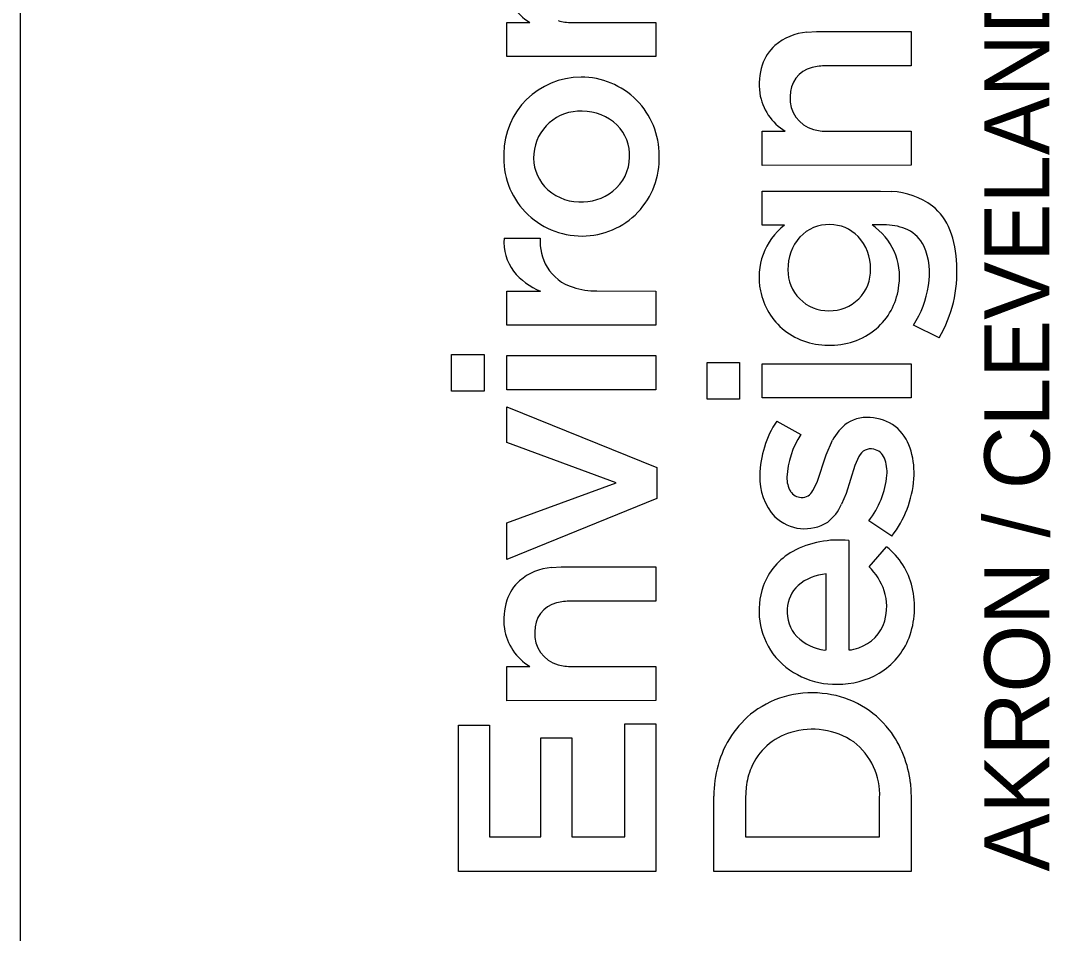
# Model space of a CAD drawing. Extents: x 0 to 34, y 0 to 22.
# Drawn here: x 32 to 32.901, y 2.584 to 3.382 of the extents above; entities that cross this region are included whole.
import ezdxf

# ---------------------------------------------------------------- set-up
doc = ezdxf.new("R2010")
doc.units = 0
doc.layers.add('SH_Border', color=7, linetype='Continuous')
doc.layers.add('SH_Data', color=7, linetype='Continuous')

msp = doc.modelspace()

# ---------------------------------------------------------------- linework, layer by layer
at = {"layer": 'SH_Border'}
msp.add_line((32, 0.5), (32, 21.5), dxfattribs=at)
at = {"layer": 'SH_Data'}
for p, q in [((32.42542, 3.38066), (32.44552, 3.38071)), ((32.42542, 3.35086), (32.42542, 3.38066)), ((32.48222, 3.38071), (32.55569, 3.38071)), ((32.55569, 3.38071), (32.55571, 3.35096)), ((32.68784, 3.3722), (32.69634, 3.37266)), ((32.69634, 3.37266), (32.77916, 3.37266)), ((32.77916, 3.37266), (32.77917, 3.34287)), ((32.55571, 3.35096), (32.42542, 3.35086)), ((32.77917, 3.34287), (32.70485, 3.3428)), ((32.64888, 3.2855), (32.66897, 3.28555)), ((32.64888, 3.25569), (32.64888, 3.2855)), ((32.70568, 3.28555), (32.77915, 3.28555)), ((32.77915, 3.28555), (32.77917, 3.25579)), ((32.77917, 3.25579), (32.64888, 3.25569)), ((32.6489, 3.20336), (32.64889, 3.23322)), ((32.64889, 3.23322), (32.75236, 3.23322)), ((32.75236, 3.23322), (32.76191, 3.23285)), ((32.66836, 3.20336), (32.6489, 3.20336)), ((32.75763, 3.20356), (32.74487, 3.20361)), ((32.42299, 3.19193), (32.45454, 3.19193)), ((32.42542, 3.14577), (32.45473, 3.14579)), ((32.42542, 3.11593), (32.42542, 3.14577)), ((32.50413, 3.14581), (32.55571, 3.14573)), ((32.55571, 3.14573), (32.55565, 3.11593)), ((32.55565, 3.11593), (32.42542, 3.11593)), ((32.8036, 3.10491), (32.7812, 3.11598)), ((32.37705, 3.05818), (32.37705, 3.09026)), ((32.37705, 3.09026), (32.40543, 3.09026)), ((32.40543, 3.09026), (32.40543, 3.05818)), ((32.42542, 3.05942), (32.42542, 3.08928)), ((32.42542, 3.08928), (32.55571, 3.08928)), ((32.55571, 3.08928), (32.55571, 3.05942)), ((32.60051, 3.05111), (32.60051, 3.08319)), ((32.60051, 3.08319), (32.62889, 3.08319)), ((32.62889, 3.08319), (32.62889, 3.05111)), ((32.64888, 3.05234), (32.64888, 3.0822)), ((32.64888, 3.0822), (32.77917, 3.0822)), ((32.77917, 3.0822), (32.77917, 3.05234)), ((32.40543, 3.05818), (32.37705, 3.05818)), ((32.55571, 3.05942), (32.42542, 3.05942)), ((32.62889, 3.05111), (32.60051, 3.05111)), ((32.77917, 3.05234), (32.64888, 3.05234)), ((32.42542, 3.01327), (32.42542, 3.0446)), ((32.42542, 3.0446), (32.5567, 2.9913)), ((32.66151, 3.03207), (32.68268, 3.02025)), ((32.52117, 2.97798), (32.42542, 3.01327)), ((32.70483, 3.00258), (32.71036, 3.01526)), ((32.69675, 2.97868), (32.70483, 3.00258)), ((32.73342, 3.00101), (32.72985, 2.9933)), ((32.5567, 2.9913), (32.5567, 2.96441)), ((32.72985, 2.9933), (32.72213, 2.96882)), ((32.42542, 2.94294), (32.52117, 2.97798)), ((32.69299, 2.97117), (32.69675, 2.97868)), ((32.5567, 2.96441), (32.42542, 2.91086)), ((32.72213, 2.96882), (32.71822, 2.95921)), ((32.42542, 2.91086), (32.42542, 2.94294)), ((32.76214, 2.93141), (32.74198, 2.94469)), ((32.72453, 2.92747), (32.72463, 2.83195)), ((32.74228, 2.90465), (32.75768, 2.922)), ((32.46439, 2.90397), (32.47289, 2.90443)), ((32.47289, 2.90443), (32.55571, 2.90443)), ((32.55571, 2.90443), (32.55571, 2.87465)), ((32.70489, 2.83182), (32.70489, 2.89834)), ((32.55571, 2.87465), (32.4814, 2.87457)), ((32.70361, 2.83165), (32.70489, 2.83182)), ((32.42542, 2.81728), (32.44552, 2.81733)), ((32.42542, 2.78747), (32.42542, 2.81728)), ((32.48222, 2.81733), (32.55569, 2.81733)), ((32.55569, 2.81733), (32.55571, 2.78756)), ((32.55571, 2.78756), (32.42542, 2.78747)), ((32.38298, 2.63791), (32.38298, 2.76598)), ((32.38298, 2.76598), (32.41012, 2.76598)), ((32.41012, 2.76598), (32.41012, 2.66827)), ((32.52857, 2.66827), (32.52857, 2.76722)), ((32.52857, 2.76722), (32.55571, 2.76722)), ((32.55571, 2.76722), (32.55571, 2.63791)), ((32.45503, 2.66827), (32.45503, 2.75488)), ((32.45503, 2.75488), (32.48218, 2.75488)), ((32.48218, 2.75488), (32.48218, 2.66827)), ((32.77847, 2.71497), (32.77917, 2.7021)), ((32.60643, 2.63799), (32.60644, 2.704)), ((32.63465, 2.71178), (32.63407, 2.7023)), ((32.63407, 2.7023), (32.63407, 2.66838)), ((32.75149, 2.66834), (32.75153, 2.70239)), ((32.77917, 2.7021), (32.77917, 2.638)), ((32.41012, 2.66827), (32.45503, 2.66827)), ((32.48218, 2.66827), (32.52857, 2.66827)), ((32.63407, 2.66838), (32.75149, 2.66834)), ((32.55571, 2.63791), (32.38298, 2.63791)), ((32.77917, 2.638), (32.60643, 2.63799))]:
    msp.add_line(p, q, dxfattribs=at)
for points in [[(32.42542, 3.35086), (32.42542, 3.38066), (32.44552, 3.38071)], [(32.48222, 3.38071), (32.55569, 3.38071), (32.55571, 3.35096), (32.42542, 3.35086)], [(32.68784, 3.3722), (32.69634, 3.37266), (32.77916, 3.37266), (32.77917, 3.34287), (32.70485, 3.3428)], [(32.64888, 3.25569), (32.64888, 3.2855), (32.66897, 3.28555)], [(32.70568, 3.28555), (32.77915, 3.28555), (32.77917, 3.25579), (32.64888, 3.25569)], [(32.66836, 3.20336), (32.6489, 3.20336), (32.64889, 3.23322), (32.75236, 3.23322), (32.76191, 3.23285)], [(32.75763, 3.20356), (32.74487, 3.20361)], [(32.42299, 3.19193), (32.45454, 3.19193)], [(32.50413, 3.14581), (32.55571, 3.14573), (32.55565, 3.11593), (32.42542, 3.11593)], [(32.42542, 3.11593), (32.42542, 3.14577), (32.45473, 3.14579)], [(32.8036, 3.10491), (32.7812, 3.11598)], [(32.66151, 3.03207), (32.68268, 3.02025)], [(32.69299, 2.97117), (32.69675, 2.97868), (32.70483, 3.00258), (32.71036, 3.01526)], [(32.73342, 3.00101), (32.72985, 2.9933), (32.72213, 2.96882), (32.71822, 2.95921)], [(32.76214, 2.93141), (32.74198, 2.94469)], [(32.72453, 2.92747), (32.72463, 2.83195)], [(32.74228, 2.90465), (32.75768, 2.922)], [(32.46439, 2.90397), (32.47289, 2.90443), (32.55571, 2.90443), (32.55571, 2.87465), (32.4814, 2.87457)], [(32.70361, 2.83165), (32.70489, 2.83182), (32.70489, 2.89834)], [(32.42542, 2.78747), (32.42542, 2.81728), (32.44552, 2.81733)], [(32.48222, 2.81733), (32.55569, 2.81733), (32.55571, 2.78756), (32.42542, 2.78747)], [(32.77847, 2.71497), (32.77917, 2.7021), (32.77917, 2.638), (32.60643, 2.63799)], [(32.60643, 2.63799), (32.60644, 2.704)], [(32.63465, 2.71178), (32.63407, 2.7023), (32.63407, 2.66838), (32.75149, 2.66834), (32.75153, 2.70239)]]:
    msp.add_lwpolyline(points, dxfattribs=at)
for points in [[(32.37705, 3.05818), (32.37705, 3.09026), (32.40543, 3.09026), (32.40543, 3.05818)], [(32.42542, 3.05942), (32.42542, 3.08928), (32.55571, 3.08928), (32.55571, 3.05942)], [(32.60051, 3.05111), (32.60051, 3.08319), (32.62889, 3.08319), (32.62889, 3.05111)], [(32.64888, 3.05234), (32.64888, 3.0822), (32.77917, 3.0822), (32.77917, 3.05234)], [(32.42542, 2.91086), (32.42542, 2.94294), (32.52117, 2.97798), (32.42542, 3.01327), (32.42542, 3.0446), (32.5567, 2.9913), (32.5567, 2.96441)], [(32.38298, 2.63791), (32.38298, 2.76598), (32.41012, 2.76598), (32.41012, 2.66827), (32.45503, 2.66827), (32.45503, 2.75488), (32.48218, 2.75488), (32.48218, 2.66827), (32.52857, 2.66827), (32.52857, 2.76722), (32.55571, 2.76722), (32.55571, 2.63791)]]:
    msp.add_lwpolyline(points, close=True, dxfattribs=at)
for centre, radius, start, end in [((32.47027, 3.42141), 0.04763, 188.96462, 238.69865), ((32.47027, 3.42141), 0.04763, 188.96462, 238.69865), ((32.48183, 3.42286), 0.04215, 254.08913, 270.52838), ((32.48183, 3.42286), 0.04215, 254.08913, 270.52838), ((32.69216, 3.32251), 0.04988, 94.97056, 130.22484), ((32.69216, 3.32251), 0.04988, 94.97056, 130.22484), ((32.68694, 3.33085), 0.04016, 132.22383, 161.68229), ((32.68694, 3.33085), 0.04016, 132.22383, 161.68229), ((32.70217, 3.32642), 0.05602, 162.27398, 187.79173), ((32.70217, 3.32642), 0.05602, 162.27398, 187.79173), ((32.70453, 3.29679), 0.04601, 89.60515, 105.33026), ((32.70453, 3.29679), 0.04601, 89.60515, 105.33026), ((32.69828, 3.31689), 0.02498, 103.68683, 182.21395), ((32.69828, 3.31689), 0.02498, 103.68683, 182.21395), ((32.49014, 3.26543), 0.0674, 89.84756, 179.64047), ((32.49014, 3.26543), 0.0674, 89.84756, 179.64047), ((32.49057, 3.26474), 0.0681, 359.54009, 90.21138), ((32.49057, 3.26474), 0.0681, 359.54009, 90.21138), ((32.69372, 3.32624), 0.04763, 188.96462, 238.69865), ((32.69372, 3.32624), 0.04763, 188.96462, 238.69865), ((32.7008, 3.31381), 0.02757, 175.58441, 255.13816), ((32.7008, 3.31381), 0.02757, 175.58441, 255.13816), ((32.48923, 3.26263), 0.0404, 87.04809, 175.57259), ((32.48923, 3.26263), 0.0404, 87.04809, 175.57259), ((32.49204, 3.25999), 0.04299, 45.84264, 90.98008), ((32.49204, 3.25999), 0.04299, 45.84264, 90.98008), ((32.49458, 3.26421), 0.03821, 357.88569, 44.15902), ((32.49458, 3.26421), 0.03821, 357.88569, 44.15902), ((32.70529, 3.32769), 0.04215, 254.08913, 270.52838), ((32.70529, 3.32769), 0.04215, 254.08913, 270.52838), ((32.49083, 3.26209), 0.06819, 176.8344, 270.40384), ((32.49083, 3.26209), 0.06819, 176.8344, 270.40384), ((32.48729, 3.2625), 0.03848, 175.15378, 221.14706), ((32.48729, 3.2625), 0.03848, 175.15378, 221.14706), ((32.49123, 3.26139), 0.06749, 270.06243, 2.37759), ((32.49123, 3.26139), 0.06749, 270.06243, 2.37759), ((32.49446, 3.26318), 0.0383, 308.28936, 359.43468), ((32.49446, 3.26318), 0.0383, 308.28936, 359.43468), ((32.48919, 3.26607), 0.04228, 223.09994, 268.80895), ((32.48919, 3.26607), 0.04228, 223.09994, 268.80895), ((32.49096, 3.2679), 0.04418, 266.56515, 308.06078), ((32.49096, 3.2679), 0.04418, 266.56515, 308.06078), ((32.75907, 3.16789), 0.06503, 53.40344, 87.49062), ((32.75907, 3.16789), 0.06503, 53.40344, 87.49062), ((32.76517, 3.18039), 0.05141, 21.60748, 50.5577), ((32.76517, 3.18039), 0.05141, 21.60748, 50.5577), ((32.70292, 3.15813), 0.05692, 127.37482, 192.22468), ((32.70292, 3.15813), 0.05692, 127.37482, 192.22468), ((32.70693, 3.16927), 0.0346, 88.47302, 136.42562), ((32.70693, 3.16927), 0.0346, 88.47302, 136.42562), ((32.70814, 3.16963), 0.03424, 44.27195, 90.47623), ((32.70814, 3.16963), 0.03424, 44.27195, 90.47623), ((32.71421, 3.15829), 0.05472, 352.1125, 55.92295), ((32.71421, 3.15829), 0.05472, 352.1125, 55.92295), ((32.75666, 3.15725), 0.04633, 65.01687, 88.8011), ((32.75666, 3.15725), 0.04633, 65.01687, 88.8011), ((32.7626, 3.17155), 0.03085, 26.26808, 63.80301), ((32.7626, 3.17155), 0.03085, 26.26808, 63.80301), ((32.73069, 3.16714), 0.08835, 1.15143, 21.3627), ((32.73069, 3.16714), 0.08835, 1.15143, 21.3627), ((32.46616, 3.18882), 0.04329, 175.87313, 216.34747), ((32.46616, 3.18882), 0.04329, 175.87313, 216.34747), ((32.50087, 3.18948), 0.04639, 176.9688, 209.60636), ((32.50087, 3.18948), 0.04639, 176.9688, 209.60636), ((32.71141, 3.16602), 0.0401, 137.46739, 182.33237), ((32.71141, 3.16602), 0.0401, 137.46739, 182.33237), ((32.70368, 3.166), 0.03996, 358.57141, 43.53765), ((32.70368, 3.166), 0.03996, 358.57141, 43.53765), ((32.73565, 3.16154), 0.05953, 349.30734, 23.43071), ((32.73565, 3.16154), 0.05953, 349.30734, 23.43071), ((32.47466, 3.19716), 0.05511, 218.09809, 248.7907), ((32.47466, 3.19716), 0.05511, 218.09809, 248.7907), ((32.49514, 3.18814), 0.04079, 211.94466, 253.2028), ((32.49514, 3.18814), 0.04079, 211.94466, 253.2028), ((32.70645, 3.1637), 0.03511, 178.88208, 271.08374), ((32.70645, 3.1637), 0.03511, 178.88208, 271.08374), ((32.70818, 3.16404), 0.03546, 268.27882, 1.55016), ((32.70818, 3.16404), 0.03546, 268.27882, 1.55016), ((32.70538, 3.16244), 0.11383, 329.6388, 3.25998), ((32.70538, 3.16244), 0.11383, 329.6388, 3.25998), ((32.50465, 3.2165), 0.07069, 252.46555, 269.57296), ((32.50465, 3.2165), 0.07069, 252.46555, 269.57296), ((32.70463, 3.15696), 0.05837, 190.75182, 231.28919), ((32.70463, 3.15696), 0.05837, 190.75182, 231.28919), ((32.70988, 3.15708), 0.05887, 313.74196, 353.8554), ((32.70988, 3.15708), 0.05887, 313.74196, 353.8554), ((32.70738, 3.16334), 0.08771, 327.31495, 351.57478), ((32.70738, 3.16334), 0.08771, 327.31495, 351.57478), ((32.70632, 3.16112), 0.06269, 232.46061, 272.59022), ((32.70632, 3.16112), 0.06269, 232.46061, 272.59022), ((32.70954, 3.15901), 0.06051, 269.6361, 312.70877), ((32.70954, 3.15901), 0.06051, 269.6361, 312.70877), ((32.73636, 2.98258), 0.08973, 146.53104, 178.7571), ((32.73636, 2.98258), 0.08973, 146.53104, 178.7571), ((32.74661, 2.99713), 0.04053, 125.51182, 153.41595), ((32.74661, 2.99713), 0.04053, 125.51182, 153.41595), ((32.7406, 3.0026), 0.03263, 80.17192, 122.51969), ((32.7406, 3.0026), 0.03263, 80.17192, 122.51969), ((32.74278, 2.99824), 0.03667, 47.79344, 84.68918), ((32.74278, 2.99824), 0.03667, 47.79344, 84.68918), ((32.74519, 2.9789), 0.07495, 146.51121, 176.91007), ((32.74519, 2.9789), 0.07495, 146.51121, 176.91007), ((32.73788, 2.9946), 0.04267, 14.9966, 46.20632), ((32.73788, 2.9946), 0.04267, 14.9966, 46.20632), ((32.74384, 2.99631), 0.01143, 76.66094, 155.7053), ((32.74384, 2.99631), 0.01143, 76.66094, 155.7053), ((32.74397, 2.99511), 0.01256, 21.5098, 78.52618), ((32.74397, 2.99511), 0.01256, 21.5098, 78.52618), ((32.71044, 2.98674), 0.07121, 355.83062, 15.39138), ((32.71044, 2.98674), 0.07121, 355.83062, 15.39138), ((32.72592, 2.98766), 0.03209, 354.57264, 22.06805), ((32.72592, 2.98766), 0.03209, 354.57264, 22.06805), ((32.69666, 2.98238), 0.05005, 177.53659, 222.79318), ((32.69666, 2.98238), 0.05005, 177.53659, 222.79318), ((32.6931, 2.98233), 0.02276, 178.47474, 211.08679), ((32.6931, 2.98233), 0.02276, 178.47474, 211.08679), ((32.68248, 2.99149), 0.0757, 321.81101, 354.79685), ((32.68248, 2.99149), 0.0757, 321.81101, 354.79685), ((32.68952, 2.9882), 0.09219, 321.9777, 355.87384), ((32.68952, 2.9882), 0.09219, 321.9777, 355.87384), ((32.68331, 2.9767), 0.01148, 212.23676, 268.37769), ((32.68331, 2.9767), 0.01148, 212.23676, 268.37769), ((32.68342, 2.97589), 0.01067, 267.71603, 333.73375), ((32.68342, 2.97589), 0.01067, 267.71603, 333.73375), ((32.68098, 2.9758), 0.04077, 308.08772, 335.98736), ((32.68098, 2.9758), 0.04077, 308.08772, 335.98736), ((32.68599, 2.97535), 0.0375, 225.98539, 302.47965), ((32.68599, 2.97535), 0.0375, 225.98539, 302.47965), ((32.7152, 2.84414), 0.08384, 83.61499, 118.28755), ((32.7152, 2.84414), 0.08384, 83.61499, 118.28755), ((32.71744, 2.87167), 0.06443, 13.53365, 51.36148), ((32.71744, 2.87167), 0.06443, 13.53365, 51.36148), ((32.70239, 2.86906), 0.05583, 118.83082, 160.62438), ((32.70239, 2.86906), 0.05583, 118.83082, 160.62438), ((32.46871, 2.85428), 0.04988, 94.96958, 130.22249), ((32.46871, 2.85428), 0.04988, 94.96958, 130.22249), ((32.70378, 2.86556), 0.05486, 19.03571, 45.44059), ((32.70378, 2.86556), 0.05486, 19.03571, 45.44059), ((32.46348, 2.86263), 0.04015, 132.22192, 161.68183), ((32.46348, 2.86263), 0.04015, 132.22192, 161.68183), ((32.70785, 2.85609), 0.04235, 94.00805, 130.88169), ((32.70785, 2.85609), 0.04235, 94.00805, 130.88169), ((32.71041, 2.86612), 0.06437, 160.52012, 215.78311), ((32.71041, 2.86612), 0.06437, 160.52012, 215.78311), ((32.70048, 2.86628), 0.02985, 132.98507, 177.179), ((32.70048, 2.86628), 0.02985, 132.98507, 177.179), ((32.71069, 2.8697), 0.047, 344.60586, 17.007), ((32.71069, 2.8697), 0.047, 344.60586, 17.007), ((32.70635, 2.86921), 0.07579, 339.3542, 13.37853), ((32.70635, 2.86921), 0.07579, 339.3542, 13.37853), ((32.47872, 2.85819), 0.05601, 162.27355, 187.79185), ((32.47872, 2.85819), 0.05601, 162.27355, 187.79185), ((32.48108, 2.82856), 0.04601, 89.60494, 105.3284), ((32.48108, 2.82856), 0.04601, 89.60494, 105.3284), ((32.47482, 2.84867), 0.02498, 103.68646, 182.21874), ((32.47482, 2.84867), 0.02498, 103.68646, 182.21874), ((32.7017, 2.86503), 0.03115, 175.00126, 223.28301), ((32.7017, 2.86503), 0.03115, 175.00126, 223.28301), ((32.7224, 2.86715), 0.03504, 288.00773, 343.55078), ((32.7224, 2.86715), 0.03504, 288.00773, 343.55078), ((32.47026, 2.85802), 0.04762, 188.96199, 238.70369), ((32.47026, 2.85802), 0.04762, 188.96199, 238.70369), ((32.47735, 2.84558), 0.02756, 175.58538, 255.14386), ((32.47735, 2.84558), 0.02756, 175.58538, 255.14386), ((32.70891, 2.87363), 0.04231, 225.06188, 262.79738), ((32.70891, 2.87363), 0.04231, 225.06188, 262.79738), ((32.71894, 2.8652), 0.0626, 300.94269, 338.73225), ((32.71894, 2.8652), 0.0626, 300.94269, 338.73225), ((32.72474, 2.85216), 0.02021, 269.7003, 294.8711), ((32.72474, 2.85216), 0.02021, 269.7003, 294.8711), ((32.71253, 2.87054), 0.06872, 217.74516, 271.65431), ((32.71253, 2.87054), 0.06872, 217.74516, 271.65431), ((32.48183, 2.85948), 0.04215, 254.09162, 270.52835), ((32.48183, 2.85948), 0.04215, 254.09162, 270.52835), ((32.71549, 2.87241), 0.07056, 269.20477, 300.33412), ((32.71549, 2.87241), 0.07056, 269.20477, 300.33412), ((32.69229, 2.70792), 0.08641, 81.19402, 125.99844), ((32.69229, 2.70792), 0.08641, 81.19402, 125.99844), ((32.69458, 2.71132), 0.08272, 37.85208, 82.40204), ((32.69458, 2.71132), 0.08272, 37.85208, 82.40204), ((32.69387, 2.70893), 0.08654, 127.23621, 165.14796), ((32.69387, 2.70893), 0.08654, 127.23621, 165.14796), ((32.68893, 2.70782), 0.05398, 106.18808, 157.38609), ((32.68893, 2.70782), 0.05398, 106.18808, 157.38609), ((32.69279, 2.69862), 0.06389, 55.67272, 107.20935), ((32.69279, 2.69862), 0.06389, 55.67272, 107.20935), ((32.68586, 2.70567), 0.09308, 5.73329, 37.30396), ((32.68586, 2.70567), 0.09308, 5.73329, 37.30396), ((32.69291, 2.70499), 0.05867, 357.46616, 52.26647), ((32.69291, 2.70499), 0.05867, 357.46616, 52.26647), ((32.71426, 2.70281), 0.10783, 164.7861, 179.37039), ((32.71426, 2.70281), 0.10783, 164.7861, 179.37039), ((32.69829, 2.70389), 0.06412, 157.35705, 172.92755), ((32.69829, 2.70389), 0.06412, 157.35705, 172.92755)]:
    msp.add_arc(centre, radius, start, end, dxfattribs=at)

# ---------------------------------------------------------------- texts
msp.add_text('AKRON / CLEVELAND / COLUMBUS', height=0.056969, rotation=90, dxfattribs=at).set_placement((32.90012, 2.638))

doc.saveas('drawing.dxf')
